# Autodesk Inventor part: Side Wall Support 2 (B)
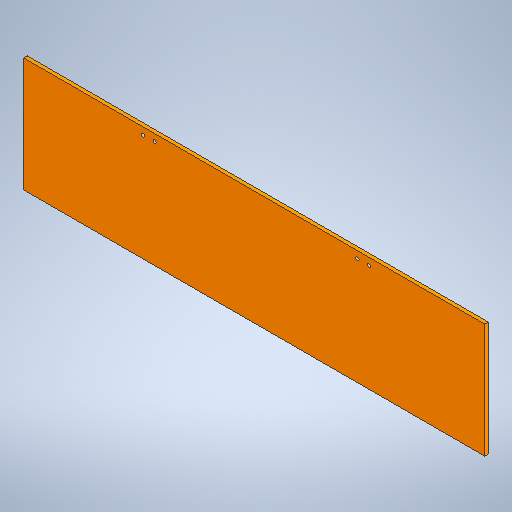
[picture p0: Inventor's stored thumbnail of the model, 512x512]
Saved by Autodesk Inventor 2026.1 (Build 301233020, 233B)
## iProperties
Created: 2026-11
Part Number: Side Wall Support 2 (B)
Material: Generic
Document SubType Name: Modeling
Designer: hp
Density: 1 g/cm^3
Appearance: Default
Author: hp
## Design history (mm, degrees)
sketch "Sketch1"
  geometry: L1 (0, 0)-(645, 0); L2 (645, 0)-(645, 160); L3 (645, 160)-(0, 160); L4 (0, 160)-(0, 0)
  constraints: 8 end point, 2 parallel, 1 horizontal, 1 perpendicular
  dimensions: "d0" = 645 distance of L3.end L2.end; "d1" = 160 distance of L2.end L1.end
extrude "Extrusion1" new body sketch "Sketch1" distance "d2" = 5; taper "d3" = 0 deg
sketch "Sketch2"
  geometry: 4 further points
hole "Hole1" sketch "Sketch2" at (-483, 150), (-467, 150), (-183, 150), (-167, 150) diameter "d4" = 4.5; stored, may be unused: countersink angle "d8" = 90 deg, drill point angle "d10" = 0 deg; dims "d5" = 6, "d6" = 4, "d7" = 2, "d9" = 8
body "Solid1"
